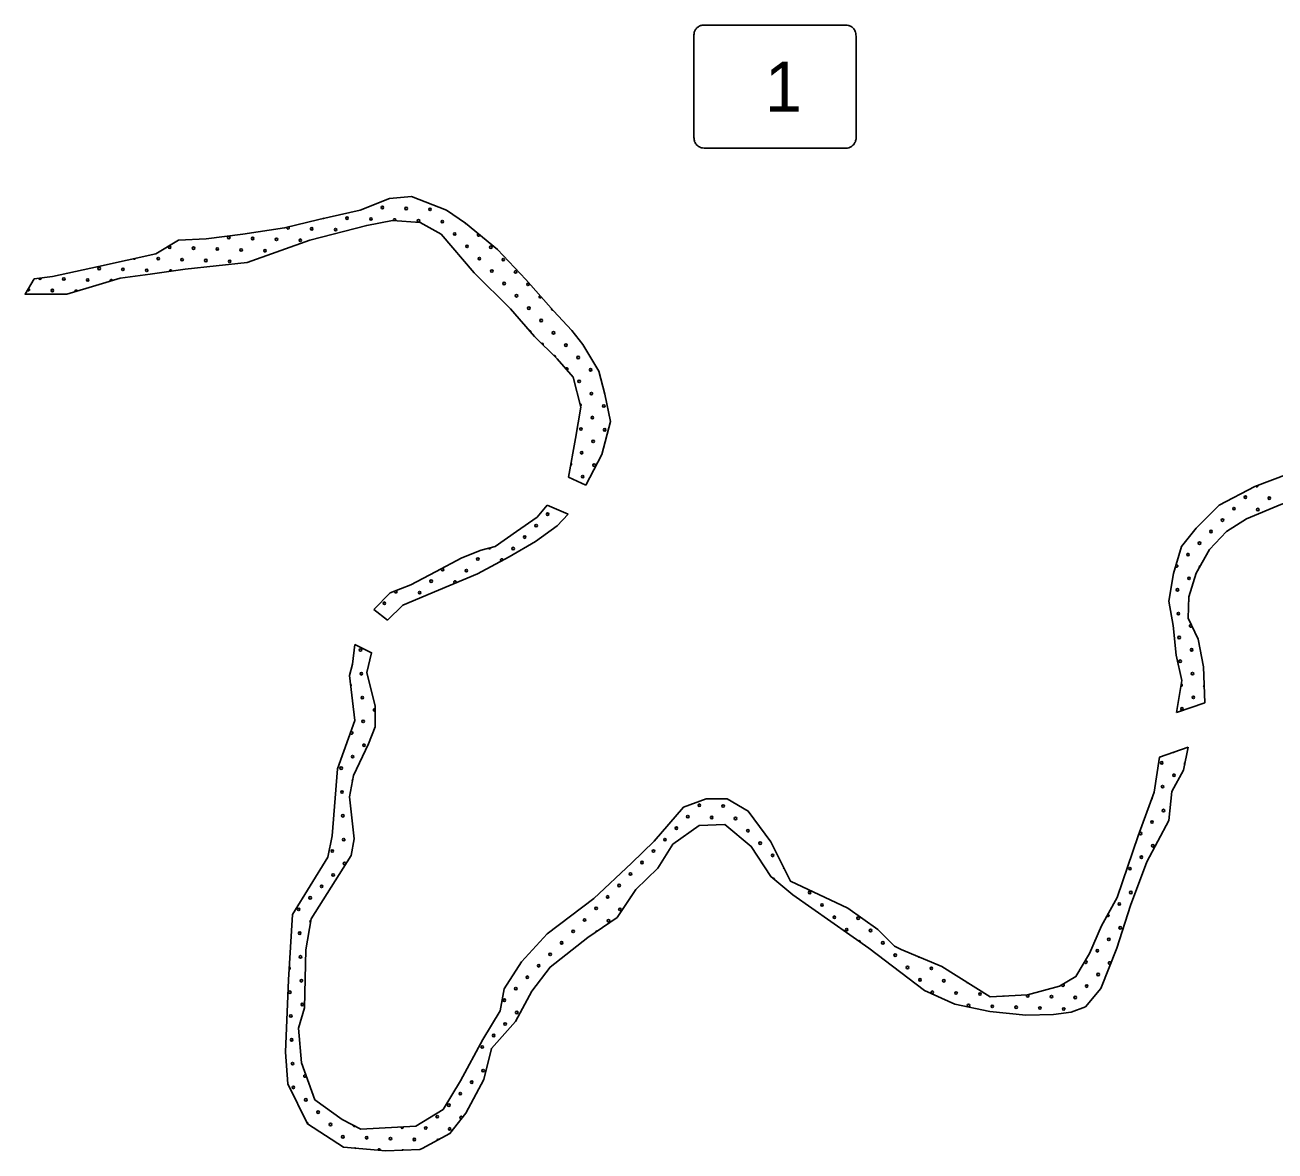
# Model space of a CAD drawing. Extents: x 1612280 to 1883141, y 560852 to 780851.
# Drawn here: x 1673931 to 1684509, y 630405 to 639937 of the extents above; entities that cross this region are included whole.
import ezdxf

# ---------------------------------------------------------------- set-up
doc = ezdxf.new("R2010")
doc.units = 0
for name, color, linetype in [('DESIGN - ROW - Slope Lines', 7, 'Continuous'), ('DESIGN - SCRATCH - User 1', 7, 'Continuous'), ('DESIGN - TRAFFIC CONTROL PERMANENT - Pavement Marking Text', 7, 'Continuous')]:
    doc.layers.add(name, color=color, linetype=linetype)

msp = doc.modelspace()

# ---------------------------------------------------------------- linework, layer by layer
at = {"layer": 'DESIGN - ROW - Slope Lines'}
msp.add_line((1679591, 639836), (1679591, 639004), dxfattribs=at)
msp.add_line((1679591, 639836), (1679591, 639004), dxfattribs=at)
for points in [[(1680963, 639825), (1680963, 639833), (1680963, 639841), (1680962, 639856), (1680961, 639866), (1680959, 639877), (1680957, 639883), (1680954, 639890), (1680949, 639897), (1680944, 639905), (1680939, 639910), (1680933, 639916), (1680929, 639919), (1680922, 639924), (1680917, 639927), (1680909, 639931), (1680903, 639933), (1680896, 639934), (1680886, 639936), (1680878, 639937), (1680870, 639937), (1680857, 639937), (1680848, 639937), (1679690, 639937), (1679681, 639937), (1679671, 639937), (1679662, 639935), (1679653, 639934), (1679648, 639932), (1679641, 639929), (1679635, 639926), (1679629, 639923), (1679620, 639916), (1679614, 639910), (1679609, 639904), (1679605, 639899), (1679600, 639889), (1679596, 639882), (1679594, 639877), (1679594, 639873), (1679593, 639870), (1679592, 639863), (1679591, 639853), (1679591, 639845), (1679591, 639839), (1679591, 639821)], [(1680963, 639825), (1680963, 639833), (1680963, 639841), (1680962, 639856), (1680961, 639866), (1680959, 639877), (1680957, 639883), (1680954, 639890), (1680949, 639897), (1680944, 639905), (1680939, 639910), (1680933, 639916), (1680929, 639919), (1680922, 639924), (1680917, 639927), (1680909, 639931), (1680903, 639933), (1680896, 639934), (1680886, 639936), (1680878, 639937), (1680870, 639937), (1680857, 639937), (1680848, 639937), (1679690, 639937), (1679681, 639937), (1679671, 639937), (1679662, 639935), (1679653, 639934), (1679648, 639932), (1679641, 639929), (1679635, 639926), (1679629, 639923), (1679620, 639916), (1679614, 639910), (1679609, 639904), (1679605, 639899), (1679600, 639889), (1679596, 639882), (1679594, 639877), (1679594, 639873), (1679593, 639870), (1679592, 639863), (1679591, 639853), (1679591, 639845), (1679591, 639839), (1679591, 639821)], [(1680854, 638895), (1680874, 638895), (1680891, 638895), (1680901, 638898), (1680914, 638903), (1680925, 638909), (1680934, 638916), (1680942, 638924), (1680948, 638932), (1680954, 638942), (1680958, 638949), (1680960, 638956), (1680962, 638964), (1680963, 638972), (1680963, 638982), (1680963, 639005), (1680963, 639825)], [(1680854, 638895), (1680874, 638895), (1680891, 638895), (1680901, 638898), (1680914, 638903), (1680925, 638909), (1680934, 638916), (1680942, 638924), (1680948, 638932), (1680954, 638942), (1680958, 638949), (1680960, 638956), (1680962, 638964), (1680963, 638972), (1680963, 638982), (1680963, 639005), (1680963, 639825)], [(1679591, 639004), (1679591, 638995), (1679591, 638985), (1679592, 638976), (1679593, 638966), (1679595, 638957), (1679597, 638949), (1679601, 638942), (1679605, 638935), (1679611, 638927), (1679616, 638921), (1679623, 638915), (1679630, 638909), (1679638, 638905), (1679647, 638901), (1679656, 638898), (1679663, 638897), (1679678, 638895), (1679697, 638895), (1680854, 638895)], [(1679591, 639004), (1679591, 638995), (1679591, 638985), (1679592, 638976), (1679593, 638966), (1679595, 638957), (1679597, 638949), (1679601, 638942), (1679605, 638935), (1679611, 638927), (1679616, 638921), (1679623, 638915), (1679630, 638909), (1679638, 638905), (1679647, 638901), (1679656, 638898), (1679663, 638897), (1679678, 638895), (1679697, 638895), (1680854, 638895)]]:
    msp.add_lwpolyline(points, dxfattribs=at)
at = {"layer": 'DESIGN - SCRATCH - User 1'}
for points in [[(1678677, 636042), (1678812, 636302), (1678885, 636582), (1678838, 636811), (1678786, 637008), (1678651, 637232), (1678557, 637351), (1678402, 637518), (1678168, 637783), (1677929, 638037), (1677659, 638261), (1677498, 638370), (1677202, 638484), (1677015, 638469), (1676766, 638370), (1676418, 638292), (1676127, 638219), (1675774, 638167), (1675463, 638126), (1675229, 638115), (1675037, 638001), (1674554, 637892), (1674164, 637809), (1674009, 637788)], [(1678677, 636042), (1678812, 636302), (1678885, 636582), (1678838, 636811), (1678786, 637008), (1678651, 637232), (1678557, 637351), (1678402, 637518), (1678168, 637783), (1677929, 638037), (1677659, 638261), (1677498, 638370), (1677202, 638484), (1677015, 638469), (1676766, 638370), (1676418, 638292), (1676127, 638219), (1675774, 638167), (1675463, 638126), (1675229, 638115), (1675037, 638001), (1674554, 637892), (1674164, 637809), (1674009, 637788)], [(1674009, 637788), (1673931, 637658), (1674284, 637658), (1674559, 637741), (1674736, 637793), (1674990, 637829), (1675286, 637871), (1675810, 637928), (1676340, 638115), (1676823, 638240), (1677041, 638282), (1677275, 638266)], [(1674009, 637788), (1673931, 637658), (1674284, 637658), (1674559, 637741), (1674736, 637793), (1674990, 637829), (1675286, 637871), (1675810, 637928), (1676340, 638115), (1676823, 638240), (1677041, 638282), (1677275, 638266)], [(1677275, 638266), (1677451, 638167), (1677732, 637840), (1678038, 637533), (1678241, 637299), (1678433, 637112), (1678568, 636956), (1678635, 636702), (1678589, 636437), (1678531, 636110), (1678677, 636042)], [(1677275, 638266), (1677451, 638167), (1677732, 637840), (1678038, 637533), (1678241, 637299), (1678433, 637112), (1678568, 636956), (1678635, 636702), (1678589, 636437), (1678531, 636110), (1678677, 636042)], [(1683675, 634117), (1683721, 634389), (1683671, 634602), (1683647, 634854), (1683609, 635060), (1683651, 635293), (1683717, 635522), (1683841, 635677), (1684035, 635871), (1684337, 636030), (1684613, 636134), (1684888, 636220), (1685229, 636208), (1685481, 636181), (1685721, 636100), (1685830, 636045), (1685989, 635902), (1686113, 635754), (1686268, 635471), (1686419, 635157), (1686629, 634781), (1686609, 634734)], [(1683675, 634117), (1683721, 634389), (1683671, 634602), (1683647, 634854), (1683609, 635060), (1683651, 635293), (1683717, 635522), (1683841, 635677), (1684035, 635871), (1684337, 636030), (1684613, 636134), (1684888, 636220), (1685229, 636208), (1685481, 636181), (1685721, 636100), (1685830, 636045), (1685989, 635902), (1686113, 635754), (1686268, 635471), (1686419, 635157), (1686629, 634781), (1686609, 634734)], [(1684775, 635951), (1684558, 635878), (1684268, 635758), (1684097, 635650), (1683954, 635498), (1683841, 635297), (1683779, 635095), (1683775, 634916), (1683857, 634738), (1683903, 634505), (1683915, 634199)], [(1684775, 635951), (1684558, 635878), (1684268, 635758), (1684097, 635650), (1683954, 635498), (1683841, 635297), (1683779, 635095), (1683775, 634916), (1683857, 634738), (1683903, 634505), (1683915, 634199)], [(1676882, 634989), (1677021, 635131), (1677195, 635199), (1677405, 635308), (1677626, 635427), (1677790, 635492), (1677909, 635523), (1678089, 635649), (1678266, 635771), (1678350, 635872)], [(1676882, 634989), (1677021, 635131), (1677195, 635199), (1677405, 635308), (1677626, 635427), (1677790, 635492), (1677909, 635523), (1678089, 635649), (1678266, 635771), (1678350, 635872)], [(1678350, 635872), (1678528, 635795)], [(1678350, 635872), (1678528, 635795)], [(1678528, 635795), (1678433, 635697), (1678250, 635564), (1678029, 635435), (1677760, 635292), (1677430, 635153), (1677127, 635027), (1676999, 634898)], [(1678528, 635795), (1678433, 635697), (1678250, 635564), (1678029, 635435), (1677760, 635292), (1677430, 635153), (1677127, 635027), (1676999, 634898)], [(1676999, 634898), (1676882, 634989)], [(1676999, 634898), (1676882, 634989)], [(1676722, 634693), (1676703, 634527), (1676678, 634431), (1676722, 634048), (1676576, 633640), (1676531, 633072), (1676493, 632893), (1676193, 632408), (1676161, 631853), (1676136, 631241), (1676155, 630973), (1676321, 630635), (1676627, 630437), (1676984, 630405), (1677271, 630418), (1677291, 630427)], [(1676722, 634693), (1676703, 634527), (1676678, 634431), (1676722, 634048), (1676576, 633640), (1676531, 633072), (1676493, 632893), (1676193, 632408), (1676161, 631853), (1676136, 631241), (1676155, 630973), (1676321, 630635), (1676627, 630437), (1676984, 630405), (1677271, 630418), (1677291, 630427)], [(1677239, 630615), (1676773, 630590), (1676614, 630673), (1676384, 630839), (1676270, 631151), (1676244, 631445), (1676295, 631617), (1676308, 632109), (1676352, 632370), (1676690, 632906), (1676716, 633047), (1676678, 633404), (1676710, 633583), (1676837, 633851), (1676895, 633997), (1676895, 634170), (1676824, 634457), (1676863, 634623), (1676722, 634693)], [(1677239, 630615), (1676773, 630590), (1676614, 630673), (1676384, 630839), (1676270, 631151), (1676244, 631445), (1676295, 631617), (1676308, 632109), (1676352, 632370), (1676690, 632906), (1676716, 633047), (1676678, 633404), (1676710, 633583), (1676837, 633851), (1676895, 633997), (1676895, 634170), (1676824, 634457), (1676863, 634623), (1676722, 634693)], [(1683915, 634199), (1683675, 634117)], [(1683915, 634199), (1683675, 634117)], [(1683775, 633823), (1683530, 633738), (1683485, 633443), (1683350, 633072), (1683174, 632552), (1683039, 632312), (1682939, 632076), (1682824, 631881), (1682684, 631801), (1682414, 631726), (1682099, 631711), (1681689, 631966), (1681344, 632111), (1681288, 632140)], [(1683775, 633823), (1683530, 633738), (1683485, 633443), (1683350, 633072), (1683174, 632552), (1683039, 632312), (1682939, 632076), (1682824, 631881), (1682684, 631801), (1682414, 631726), (1682099, 631711), (1681689, 631966), (1681344, 632111), (1681288, 632140)], [(1681798, 631649), (1682094, 631586), (1682399, 631556), (1682634, 631561), (1682784, 631581), (1682904, 631626), (1683034, 631781), (1683169, 632121), (1683285, 632482), (1683425, 632852), (1683610, 633203), (1683635, 633448), (1683735, 633628), (1683775, 633823)], [(1681798, 631649), (1682094, 631586), (1682399, 631556), (1682634, 631561), (1682784, 631581), (1682904, 631626), (1683034, 631781), (1683169, 632121), (1683285, 632482), (1683425, 632852), (1683610, 633203), (1683635, 633448), (1683735, 633628), (1683775, 633823)], [(1681288, 632140), (1681148, 632281), (1680893, 632460), (1680408, 632689), (1680242, 633021), (1680051, 633283), (1679872, 633385), (1679694, 633385), (1679503, 633315), (1679254, 633027), (1679063, 632842), (1678744, 632542), (1678348, 632243), (1678132, 632006), (1677985, 631777), (1677953, 631592), (1677806, 631349), (1677615, 630998), (1677468, 630756), (1677239, 630615)], [(1681288, 632140), (1681148, 632281), (1680893, 632460), (1680408, 632689), (1680242, 633021), (1680051, 633283), (1679872, 633385), (1679694, 633385), (1679503, 633315), (1679254, 633027), (1679063, 632842), (1678744, 632542), (1678348, 632243), (1678132, 632006), (1677985, 631777), (1677953, 631592), (1677806, 631349), (1677615, 630998), (1677468, 630756), (1677239, 630615)], [(1677291, 630427), (1677526, 630552), (1677660, 630724), (1677813, 631011), (1677877, 631273), (1678081, 631502), (1678221, 631758), (1678374, 631962), (1678693, 632211), (1678941, 632383), (1679101, 632619), (1679286, 632798), (1679413, 633002), (1679637, 633161), (1679853, 633168), (1680077, 632983), (1680242, 632728), (1680427, 632574), (1681071, 632121), (1681543, 631764), (1681798, 631649)], [(1677291, 630427), (1677526, 630552), (1677660, 630724), (1677813, 631011), (1677877, 631273), (1678081, 631502), (1678221, 631758), (1678374, 631962), (1678693, 632211), (1678941, 632383), (1679101, 632619), (1679286, 632798), (1679413, 633002), (1679637, 633161), (1679853, 633168), (1680077, 632983), (1680242, 632728), (1680427, 632574), (1681071, 632121), (1681543, 631764), (1681798, 631649)]]:
    msp.add_lwpolyline(points, dxfattribs=at)
at = {"layer": 'DESIGN - TRAFFIC CONTROL PERMANENT - Pavement Marking Text'}
for centre in [(1676955, 638392), (1676955, 638392), (1677156, 638384), (1677156, 638384), (1677358, 638377), (1677358, 638377), (1676656, 638302), (1676656, 638302), (1676858, 638295), (1676858, 638295), (1677261, 638280), (1677261, 638280), (1677462, 638272), (1677462, 638272), (1676357, 638212), (1676357, 638212), (1676559, 638205), (1676559, 638205), (1677567, 638168), (1677567, 638168), (1675155, 638056), (1675155, 638056), (1675655, 638138), (1675655, 638138), (1675857, 638130), (1675857, 638130), (1676059, 638123), (1676059, 638123), (1676260, 638115), (1676260, 638115), (1677671, 638063), (1677671, 638063), (1677873, 638056), (1677873, 638056), (1675058, 637959), (1675058, 637959), (1675260, 637951), (1675260, 637951), (1675357, 638048), (1675357, 638048), (1675558, 638041), (1675558, 638041), (1675760, 638033), (1675760, 638033), (1675962, 638026), (1675962, 638026), (1677776, 637959), (1677776, 637959), (1677978, 637951), (1677978, 637951), (1674558, 637876), (1674558, 637876), (1674759, 637869), (1674759, 637869), (1674961, 637861), (1674961, 637861), (1675461, 637944), (1675461, 637944), (1675663, 637936), (1675663, 637936), (1677881, 637854), (1677881, 637854), (1678082, 637847), (1678082, 637847), (1674259, 637787), (1674259, 637787), (1674461, 637779), (1674461, 637779), (1677985, 637749), (1677985, 637749), (1678187, 637742), (1678187, 637742), (1674162, 637690), (1674162, 637690), (1678090, 637645), (1678090, 637645), (1678194, 637540), (1678194, 637540), (1678299, 637436), (1678299, 637436), (1678403, 637331), (1678403, 637331), (1678508, 637227), (1678508, 637227), (1678612, 637122), (1678612, 637122), (1678717, 637018), (1678717, 637018), (1678620, 636921), (1678620, 636921), (1678724, 636816), (1678724, 636816), (1678829, 636712), (1678829, 636712), (1678732, 636614), (1678732, 636614), (1678635, 636517), (1678635, 636517), (1678836, 636510), (1678836, 636510), (1678739, 636413), (1678739, 636413), (1678642, 636316), (1678642, 636316), (1678747, 636211), (1678747, 636211), (1678650, 636114), (1678650, 636114), (1684258, 635940), (1684258, 635940), (1684161, 635843), (1684161, 635843), (1684363, 635835), (1684363, 635835), (1684460, 635932), (1684460, 635932), (1678353, 635796), (1678353, 635796), (1684064, 635746), (1684064, 635746), (1678256, 635699), (1678256, 635699), (1683967, 635649), (1683967, 635649), (1678159, 635602), (1678159, 635602), (1683870, 635551), (1683870, 635551), (1677763, 635416), (1677763, 635416), (1678062, 635505), (1678062, 635505), (1683773, 635454), (1683773, 635454), (1677465, 635326), (1677465, 635326), (1677666, 635318), (1677666, 635318), (1677368, 635229), (1677368, 635229), (1683781, 635253), (1683781, 635253), (1677270, 635132), (1677270, 635132), (1683683, 635156), (1683683, 635156), (1676972, 635042), (1676972, 635042), (1683691, 634954), (1683691, 634954), (1683698, 634752), (1683698, 634752), (1676770, 634646), (1676770, 634646), (1683803, 634648), (1683803, 634648), (1683706, 634551), (1683706, 634551), (1676777, 634445), (1676777, 634445), (1683810, 634446), (1683810, 634446), (1676785, 634243), (1676785, 634243), (1683818, 634245), (1683818, 634245), (1683721, 634148), (1683721, 634148), (1676792, 634042), (1676792, 634042), (1676800, 633840), (1676800, 633840), (1676703, 633743), (1676703, 633743), (1676606, 633646), (1676606, 633646), (1683550, 633691), (1683550, 633691), (1683654, 633586), (1683654, 633586), (1676613, 633444), (1676613, 633444), (1683557, 633489), (1683557, 633489), (1679637, 633332), (1679637, 633332), (1679839, 633325), (1679839, 633325), (1676620, 633243), (1676620, 633243), (1679540, 633235), (1679540, 633235), (1679742, 633228), (1679742, 633228), (1679943, 633220), (1679943, 633220), (1683468, 633190), (1683468, 633190), (1683565, 633287), (1683565, 633287), (1679443, 633138), (1679443, 633138), (1680048, 633116), (1680048, 633116), (1683371, 633093), (1683371, 633093), (1676628, 633041), (1676628, 633041), (1679346, 633041), (1679346, 633041), (1680152, 633011), (1680152, 633011), (1683475, 632989), (1683475, 632989), (1676531, 632944), (1676531, 632944), (1679249, 632944), (1679249, 632944), (1680257, 632907), (1680257, 632907), (1683378, 632892), (1683378, 632892), (1676635, 632839), (1676635, 632839), (1679152, 632847), (1679152, 632847), (1683281, 632795), (1683281, 632795), (1676538, 632742), (1676538, 632742), (1679055, 632750), (1679055, 632750), (1676441, 632645), (1676441, 632645), (1678861, 632556), (1678861, 632556), (1678958, 632653), (1678958, 632653), (1680571, 632593), (1680571, 632593), (1683289, 632593), (1683289, 632593), (1676247, 632451), (1676247, 632451), (1676344, 632548), (1676344, 632548), (1678764, 632459), (1678764, 632459), (1678965, 632451), (1678965, 632451), (1680675, 632488), (1680675, 632488), (1683191, 632496), (1683191, 632496), (1678666, 632361), (1678666, 632361), (1678868, 632354), (1678868, 632354), (1680780, 632384), (1680780, 632384), (1680981, 632376), (1680981, 632376), (1676255, 632249), (1676255, 632249), (1678569, 632264), (1678569, 632264), (1680884, 632279), (1680884, 632279), (1681086, 632272), (1681086, 632272), (1683199, 632294), (1683199, 632294), (1678472, 632167), (1678472, 632167), (1681190, 632167), (1681190, 632167), (1683102, 632197), (1683102, 632197), (1676262, 632048), (1676262, 632048), (1678375, 632070), (1678375, 632070), (1681295, 632063), (1681295, 632063), (1683005, 632100), (1683005, 632100), (1678278, 631973), (1678278, 631973), (1681399, 631958), (1681399, 631958), (1681601, 631951), (1681601, 631951), (1676270, 631846), (1676270, 631846), (1678181, 631876), (1678181, 631876), (1681504, 631854), (1681504, 631854), (1681706, 631846), (1681706, 631846), (1683012, 631899), (1683012, 631899), (1676172, 631749), (1676172, 631749), (1678084, 631779), (1678084, 631779), (1681608, 631749), (1681608, 631749), (1681810, 631742), (1681810, 631742), (1682012, 631734), (1682012, 631734), (1682617, 631712), (1682617, 631712), (1682818, 631704), (1682818, 631704), (1682915, 631801), (1682915, 631801), (1676277, 631645), (1676277, 631645), (1677987, 631682), (1677987, 631682), (1681915, 631637), (1681915, 631637), (1682116, 631630), (1682116, 631630), (1682318, 631622), (1682318, 631622), (1682519, 631615), (1682519, 631615), (1682721, 631607), (1682721, 631607), (1676180, 631548), (1676180, 631548), (1678092, 631577), (1678092, 631577), (1677994, 631480), (1677994, 631480), (1676187, 631346), (1676187, 631346), (1677800, 631286), (1677800, 631286), (1677897, 631383), (1677897, 631383), (1676195, 631144), (1676195, 631144), (1677808, 631085), (1677808, 631085), (1677711, 630988), (1677711, 630988), (1676202, 630943), (1676202, 630943), (1677614, 630890), (1677614, 630890), (1676307, 630838), (1676307, 630838), (1677517, 630793), (1677517, 630793), (1676411, 630734), (1676411, 630734), (1677419, 630696), (1677419, 630696), (1676516, 630629), (1676516, 630629), (1677322, 630599), (1677322, 630599), (1677524, 630592), (1677524, 630592), (1676620, 630525), (1676620, 630525), (1676822, 630517), (1676822, 630517), (1677024, 630510), (1677024, 630510), (1677225, 630502), (1677225, 630502)]:
    msp.add_circle(centre, 10.6, dxfattribs=at)
for centre, start, end in [((1676454, 638309), 253.2165, 312.036), ((1677059, 638287), 316.4427, 215.9224), ((1676156, 638220), 158.0002, 50.0915), ((1677664, 638265), 180.7701, 284.4793), ((1677769, 638160), 93.5643, 7.2223), ((1674856, 637966), 225.2254, 340.2374), ((1675163, 637854), 6.3458, 189.6424), ((1674057, 637794), 186.8031, 8.3951), ((1674662, 637772), 14.6354, 198.1678), ((1673960, 637697), 208.795, 89.3122), ((1674364, 637682), 15.9785, 197.6374), ((1678291, 637637), 111.529, 331.2814), ((1678396, 637533), 163.9396, 278.8708), ((1678202, 637339), 331.7034, 110.0885), ((1678306, 637234), 321.3268, 130.2064), ((1678411, 637130), 332.278, 119.2553), ((1678515, 637025), 281.2512, 160.5397), ((1678821, 636913), 177.6406, 211.8256), ((1678627, 636719), 303.5752, 86.1232), ((1678545, 636219), 290.2094, 49.9938), ((1684355, 636037), 201.8439, 19.8247), ((1677860, 635513), 206.5773, 2.2827), ((1677965, 635408), 353.3581, 242.6669), ((1683676, 635357), 220.3729, 107.4986), ((1683878, 635350), 94.2392, 207.496), ((1677569, 635221), 323.5547, 262.2981), ((1677069, 635139), 127.4209, 95.4262), ((1677173, 635035), 101.2403, 123.9322), ((1683788, 635051), 155.4472, 202.0647), ((1683795, 634850), 50.6373, 358.4068), ((1683713, 634349), 265.5457, 75.0097), ((1676680, 634348), 319.3399, 53.9616), ((1683915, 634342), 123.1007, 241.2471), ((1676889, 634139), 60.4697, 299.5303), ((1676695, 633944), 185.6577, 134.83), ((1683647, 633788), 250.8345, 327.4559), ((1683752, 633683), 109.0885, 227.7427), ((1676710, 633541), 127.1959, 212.5685), ((1683460, 633392), 280.6663, 39.2689), ((1680361, 632802), 171.8482, 241.2521), ((1680264, 632705), 338.6015, 122.1398), ((1679062, 632548), 102.1852, 189.7572), ((1676352, 632347), 97.8816, 242.7553), ((1683094, 632399), 211.0522, 90.2678), ((1678771, 632257), 72.8104, 176.6133), ((1680989, 632175), 345.9615, 123.7912), ((1681496, 632055), 203.1371, 291.2455), ((1676165, 631951), 276.3532, 77.0727), ((1682908, 632003), 168.752, 130.2191), ((1683109, 631996), 4.5541, 312.1586), ((1681907, 631839), 191.0227, 285.1851), ((1682213, 631727), 262.2268, 283.2267), ((1682415, 631719), 143.5812, 54.2722), ((1682714, 631809), 162.7101, 76.8148), ((1676299, 631040), 27.6994, 12.6174), ((1677621, 630689), 353.6996, 290.5906), ((1676314, 630637), 336.4453, 89.4888), ((1676718, 630622), 165.6712, 319.3499), ((1677121, 630607), 170.8756, 15.4017), ((1677427, 630495), 49.973, 185.8943), ((1676725, 630420), 43.4409, 126.347), ((1676927, 630413), 340.6905, 189.0974), ((1677128, 630405), 38.3696, 146.7255)]:
    msp.add_arc(centre, 10.6, start, end, dxfattribs=at)

# ---------------------------------------------------------------- texts
at = {"layer": 'DESIGN - ROW - Slope Lines'}
msp.add_text('1', height=422, rotation=0.0011, dxfattribs=at).set_placement((1680192, 639204))
msp.add_text('1', height=422, rotation=0.0011, dxfattribs=at).set_placement((1680192, 639204))

doc.saveas('drawing.dxf')
